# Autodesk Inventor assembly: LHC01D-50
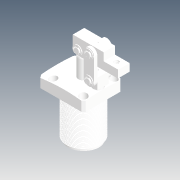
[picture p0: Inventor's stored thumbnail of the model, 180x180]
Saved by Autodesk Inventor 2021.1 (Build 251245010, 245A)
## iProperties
Created: 2019-04
Part Number: LHC01D-50
Description: STEP AP214
Document SubType Name: Assembly
Designer: user
Title: LHC01D-50.STEP
Revision Number: ÈÎºÎ
Sending System: SolidWorks 2016
Preprocessor: SwSTEP 2.0
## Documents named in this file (12)
- D:\Vault_2016\Projekty\Clamptek\Hydraulic\LHC01D\Inventor\LHC01D-50\LHC01D-50.iam
- D:\Vault_2016\Projekty\Clamptek\Hydraulic\LHC01D\Inventor\LHC01D-50\LHC01D-50(BT).ipt
- D:\Vault_2016\Projekty\Clamptek\Hydraulic\LHC01D\Inventor\LHC01D-50\CPLCU-50-05.ipt
- D:\Vault_2016\Projekty\Clamptek\Hydraulic\LHC01D\Inventor\LHC01D-50\CPLCU-50-01.ipt
- D:\Vault_2016\Projekty\Clamptek\Hydraulic\LHC01D\Inventor\LHC01D-50\CPLCU-50-02.ipt
- D:\Vault_2016\Projekty\Clamptek\Hydraulic\LHC01D\Inventor\LHC01D-50\CPLCU-50-03.ipt
- D:\Vault_2016\Projekty\Clamptek\Hydraulic\LHC01D\Inventor\LHC01D-50\CPLCU-50-04.ipt
- D:\Vault_2016\Projekty\Clamptek\Hydraulic\LHC01D\Inventor\LHC01D-50\CPLCU-50-07.ipt
- D:\Vault_2016\Projekty\Clamptek\Hydraulic\LHC01D\Inventor\LHC01D-50\CPLCU-50-08.ipt
- D:\Vault_2016\Projekty\Clamptek\Hydraulic\LHC01D\Inventor\LHC01D-50\M4ningjin_5.ipt
- D:\Vault_2016\Projekty\Clamptek\Hydraulic\LHC01D\Inventor\LHC01D-50\¶ÂÍ·_10.ipt
- D:\Vault_2016\Projekty\Clamptek\Hydraulic\LHC01D\Inventor\LHC01D-50\LHC01D050»îÈû¸Ë.ipt
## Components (24 placed, 24 different names)
1. LHC01D-50(BT)_1
2. CPLCU-50-05_2
3. CPLCU-50-01_3
4. CPLCU-50-02_4
5. CPLCU-50-02_5
6. CPLCU-50-03_6
7. CPLCU-50-04_7
8. CPLCU-50-04_8
9. CPLCU-50-07_9
10. CPLCU-50-07_10
11. CPLCU-50-07_11
12. CPLCU-50-07_12
13. CPLCU-50-07_13
14. CPLCU-50-07_14
15. CPLCU-50-08_15
16. CPLCU-50-08_16
17. CPLCU-50-08_17
18. CPLCU-50-08_18
19. CPLCU-50-08_19
20. CPLCU-50-08_20
21. M4ningjin_5_21
22. ¶ÂÍ·_10_22
23. ¶ÂÍ·_10_23
24. LHC01D050»îÈû¸Ë_24
